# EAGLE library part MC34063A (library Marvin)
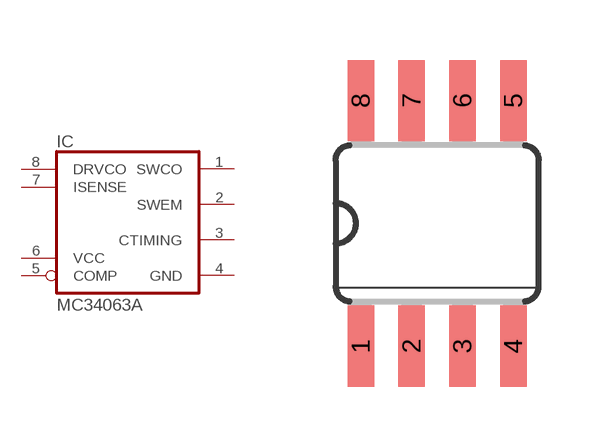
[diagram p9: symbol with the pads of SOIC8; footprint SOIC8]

Designator prefix IC

## MC34063A  [SOIC8]
1  SWCO
2  SWEM
3  CTIMING
4  GND
5  COMP
6  VCC
7  ISENSE
8  DRVCO

## Footprint SOIC8 (pad centres in mm)
smd 0.66 x 2.032: 1 -1.905,-3.073; 2 -0.635,-3.073; 3 0.635,-3.073; 4 1.905,-3.073; 5 1.905,3.073; 6 0.635,3.073; 7 -0.635,3.073; 8 -1.905,3.073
